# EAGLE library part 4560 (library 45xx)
NBCD ADDER
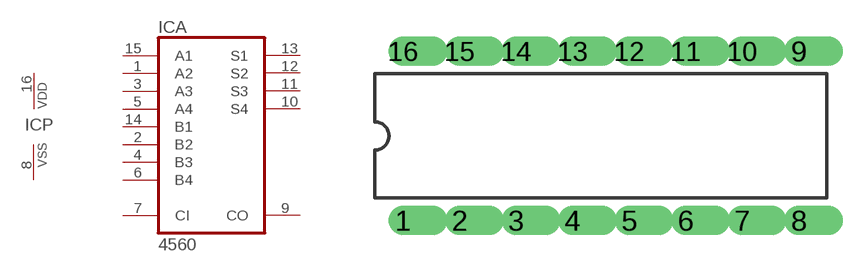
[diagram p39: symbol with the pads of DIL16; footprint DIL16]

Designator prefix IC; gates A=4560 P=PWRN

## 4560N  [DIL16]
1  A:A2  in
2  A:B2  in
3  A:A3  in
4  A:B3  in
5  A:A4  in
6  A:B4  in
7  A:CI  in
8  P:VSS  pwr
9  A:CO  out
10  A:S4  out
11  A:S3  out
12  A:S2  out
13  A:S1  out
14  A:B1  in
15  A:A1  in
16  P:VDD  pwr

## Footprint DIL16 (pad centres in mm)
Dual In Line
drill 0.813 offset: 1 -8.89,-3.81; 2 -6.35,-3.81; 3 -3.81,-3.81; 4 -1.27,-3.81; 5 1.27,-3.81; 6 3.81,-3.81; 7 6.35,-3.81; 8 8.89,-3.81; 9 8.89,3.81; 10 6.35,3.81; 11 3.81,3.81; 12 1.27,3.81; 13 -1.27,3.81; 14 -3.81,3.81; 15 -6.35,3.81; 16 -8.89,3.81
